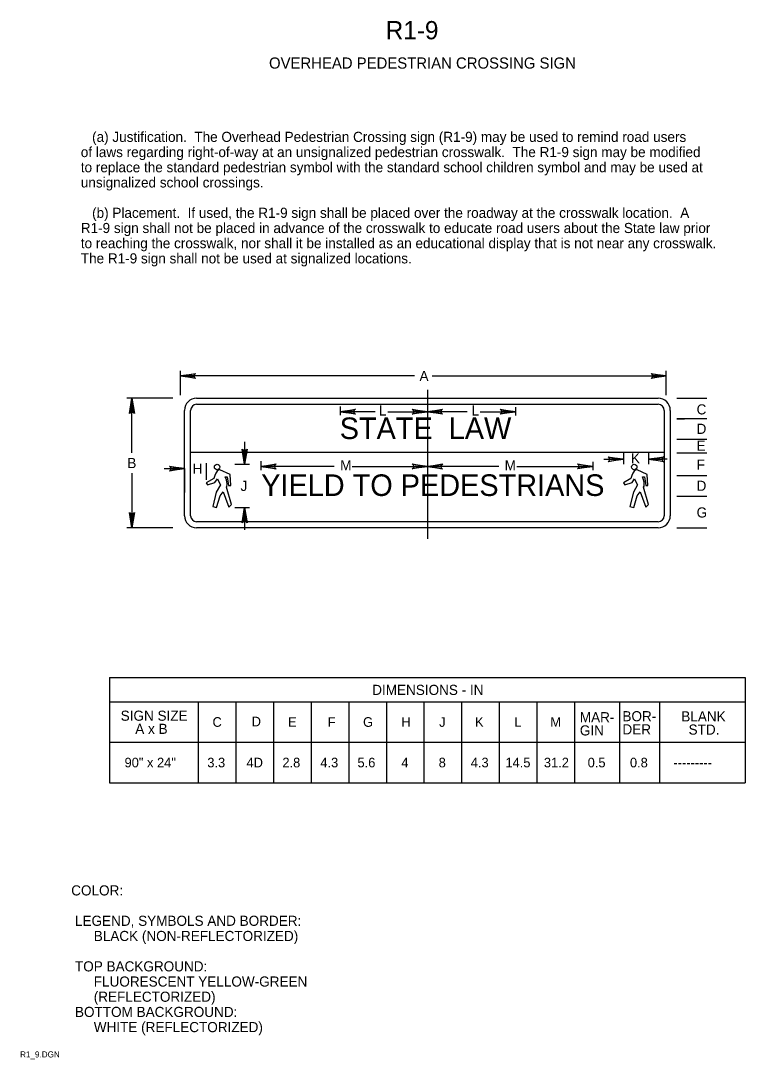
# Model space of a CAD drawing. Extents: x 0.013 to 0.192, y 0.003 to 0.259.
import ezdxf

# ---------------------------------------------------------------- set-up
doc = ezdxf.new("R2010")
doc.units = 0
for name, color, linetype in [('1', 7, 'Continuous'), ('11', 7, 'Continuous'), ('12', 7, 'Continuous'), ('2', 7, 'Continuous'), ('3', 7, 'Continuous')]:
    doc.layers.add(name, color=color, linetype=linetype)

# ---------------------------------------------------------------- blocks, each defined once
blk = doc.blocks.new('RARROW')
at = {"layer": '3'}
for p, q in [((-2.156, 0.285), (-2.2665, 0.384625)), ((-2.2665, 0.384625), (0, 0)), ((0, 0), (-2.2665, -0.379125)), ((-2.156, 0.285), (-2.075625, 0.12075)), ((0, 0), (-2.156, 0.285)), ((-2.14975, -0.2705), (0, 0)), ((-2.075625, 0.12075), (0, 0)), ((0, 0), (-2.074, -0.108)), ((-2.2665, -0.379125), (-2.14975, -0.2705)), ((-2.074, -0.108), (-2.14975, -0.2705))]:
    blk.add_line(p, q, dxfattribs=at)

msp = doc.modelspace()

# ---------------------------------------------------------------- linework, layer by layer
at = {"layer": '11'}
for p, q in [((0.05612, 0.16599), (0.17012, 0.16599)), ((0.05312, 0.13699), (0.05312, 0.16299)), ((0.17313, 0.16299), (0.17313, 0.13699)), ((0.17012, 0.13399), (0.05612, 0.13399))]:
    msp.add_line(p, q, dxfattribs=at)
for centre, start, end in [((0.05612, 0.16299), 90, 180), ((0.17012, 0.16299), 0, 90), ((0.05612, 0.13699), 180, 270), ((0.17012, 0.13699), 270, 0)]:
    msp.add_arc(centre, 0.003, start, end, dxfattribs=at)
at = {"layer": '3'}
for p, q in [((0.05212, 0.16674), (0.05212, 0.17274)), ((0.17213, 0.16674), (0.17213, 0.17274)), ((0.10992, 0.17149), (0.05212, 0.17149)), ((0.11433, 0.17149), (0.17213, 0.17149)), ((0.11313, 0.16809), (0.11313, 0.13125)), ((0.05025, 0.16599), (0.03887, 0.16599)), ((0.0395, 0.16224), (0.04013, 0.16599)), ((0.04013, 0.16599), (0.03966, 0.16242)), ((0.03993, 0.16255), (0.04013, 0.16599)), ((0.04013, 0.16599), (0.0403, 0.16255)), ((0.04057, 0.16243), (0.04013, 0.16599)), ((0.04013, 0.16599), (0.04075, 0.16224)), ((0.04013, 0.15255), (0.04013, 0.16599)), ((0.05612, 0.16449), (0.17012, 0.16449)), ((0.11313, 0.16429), (0.11313, 0.16142)), ((0.17473, 0.16599), (0.18213, 0.16599)), ((0.03966, 0.16242), (0.0395, 0.16224)), ((0.03966, 0.16242), (0.03993, 0.16255)), ((0.0403, 0.16255), (0.04057, 0.16243)), ((0.04075, 0.16224), (0.04057, 0.16243)), ((0.05462, 0.13699), (0.05462, 0.16299)), ((0.09157, 0.16394), (0.09157, 0.16177)), ((0.09657, 0.16267), (0.09157, 0.16267)), ((0.10018, 0.16267), (0.09278, 0.16267)), ((0.10339, 0.16267), (0.11122, 0.16267)), ((0.11813, 0.16267), (0.11313, 0.16267)), ((0.12296, 0.16267), (0.11313, 0.16267)), ((0.12616, 0.16267), (0.13486, 0.16267)), ((0.13486, 0.16379), (0.13486, 0.16171)), ((0.17162, 0.16299), (0.17162, 0.13699)), ((0.17473, 0.16096), (0.18213, 0.16096)), ((0.17473, 0.16094), (0.17663, 0.16094)), ((0.06796, 0.15524), (0.06796, 0.1497)), ((0.17473, 0.1559), (0.17545, 0.1559)), ((0.17473, 0.1559), (0.18213, 0.1559)), ((0.05462, 0.15266), (0.17162, 0.15266)), ((0.16154, 0.15255), (0.16154, 0.14968)), ((0.16776, 0.15257), (0.16776, 0.14969)), ((0.17473, 0.1525), (0.18213, 0.1525)), ((0.05849, 0.14998), (0.05849, 0.14584)), ((0.06558, 0.1497), (0.06921, 0.1497)), ((0.06558, 0.14969), (0.06649, 0.14969)), ((0.07199, 0.15042), (0.07199, 0.14825)), ((0.07699, 0.14914), (0.07199, 0.14914)), ((0.09012, 0.14914), (0.07321, 0.14914)), ((0.09454, 0.14914), (0.11122, 0.14914)), ((0.11313, 0.15077), (0.11313, 0.14789)), ((0.11813, 0.14914), (0.11313, 0.14914)), ((0.13075, 0.14914), (0.11313, 0.14914)), ((0.13521, 0.14914), (0.15396, 0.14914)), ((0.15396, 0.15026), (0.15396, 0.14819)), ((0.15675, 0.15093), (0.1615, 0.15093)), ((0.17233, 0.15094), (0.16776, 0.15094)), ((0.17233, 0.15094), (0.16776, 0.15094)), ((0.04013, 0.14751), (0.04013, 0.134)), ((0.04813, 0.14861), (0.05312, 0.14861)), ((0.05312, 0.14861), (0.05312, 0.14274)), ((0.06058, 0.14692), (0.06035, 0.14614)), ((0.06084, 0.14749), (0.06058, 0.14692)), ((0.06115, 0.14802), (0.06084, 0.14749)), ((0.06114, 0.14801), (0.06118, 0.14805)), ((0.06126, 0.14812), (0.06115, 0.14802)), ((0.06188, 0.14829), (0.06126, 0.14812)), ((0.06438, 0.14717), (0.06188, 0.14829)), ((0.06319, 0.1466), (0.06368, 0.14661)), ((0.06347, 0.14581), (0.06319, 0.1466)), ((0.06368, 0.14661), (0.06402, 0.14445)), ((0.06457, 0.14443), (0.06438, 0.14717)), ((0.16363, 0.14692), (0.1634, 0.14614)), ((0.16389, 0.14749), (0.16363, 0.14692)), ((0.1642, 0.14802), (0.16389, 0.14749)), ((0.16419, 0.14801), (0.16423, 0.14805)), ((0.16432, 0.14812), (0.1642, 0.14802)), ((0.16493, 0.14829), (0.16432, 0.14812)), ((0.16743, 0.14717), (0.16493, 0.14829)), ((0.16624, 0.1466), (0.16673, 0.14661)), ((0.16652, 0.14581), (0.16624, 0.1466)), ((0.16673, 0.14661), (0.16707, 0.14445)), ((0.16762, 0.14443), (0.16743, 0.14717)), ((0.17473, 0.14689), (0.18213, 0.14689)), ((0.05881, 0.14462), (0.06064, 0.14522)), ((0.06064, 0.14522), (0.06123, 0.14606)), ((0.06198, 0.14459), (0.06096, 0.14283)), ((0.06123, 0.14606), (0.06148, 0.14549)), ((0.06148, 0.14549), (0.06198, 0.14459)), ((0.06359, 0.14526), (0.06347, 0.14581)), ((0.06349, 0.14403), (0.0636, 0.14427)), ((0.06471, 0.13972), (0.06349, 0.14403)), ((0.06363, 0.14493), (0.06359, 0.14526)), ((0.0636, 0.14427), (0.06365, 0.14464)), ((0.06365, 0.14464), (0.06363, 0.14493)), ((0.06402, 0.14445), (0.06457, 0.14443)), ((0.16187, 0.14462), (0.1637, 0.14522)), ((0.1637, 0.14522), (0.16428, 0.14606)), ((0.16503, 0.14459), (0.16402, 0.14283)), ((0.16428, 0.14606), (0.16453, 0.14549)), ((0.16453, 0.14549), (0.16503, 0.14459)), ((0.16665, 0.14526), (0.16652, 0.14581)), ((0.16654, 0.14403), (0.16666, 0.14427)), ((0.16776, 0.13972), (0.16654, 0.14403)), ((0.16669, 0.14493), (0.16665, 0.14526)), ((0.16666, 0.14427), (0.1667, 0.14464)), ((0.1667, 0.14464), (0.16669, 0.14493)), ((0.16707, 0.14445), (0.16762, 0.14443)), ((0.06096, 0.14283), (0.0601, 0.1393)), ((0.06106, 0.13904), (0.06189, 0.14193)), ((0.06189, 0.14193), (0.06267, 0.14289)), ((0.06267, 0.14289), (0.06321, 0.14132)), ((0.06321, 0.14132), (0.06406, 0.13907)), ((0.16402, 0.14283), (0.16315, 0.1393)), ((0.16411, 0.13904), (0.16494, 0.14193)), ((0.16494, 0.14193), (0.16572, 0.14289)), ((0.16572, 0.14289), (0.16626, 0.14132)), ((0.16626, 0.14132), (0.16712, 0.13907)), ((0.17473, 0.14185), (0.18213, 0.14185)), ((0.06558, 0.13901), (0.06921, 0.13901)), ((0.06796, 0.13901), (0.06796, 0.13347)), ((0.05025, 0.134), (0.03887, 0.134)), ((0.17012, 0.13549), (0.05612, 0.13549)), ((0.17473, 0.13399), (0.18213, 0.13399)), ((0.0346, 0.09704), (0.0346, 0.07104)), ((0.0346, 0.09704), (0.19165, 0.09704)), ((0.19165, 0.09704), (0.19165, 0.07104)), ((0.0346, 0.09104), (0.19165, 0.09104)), ((0.05648, 0.09104), (0.05648, 0.07104)), ((0.06578, 0.09104), (0.06578, 0.07104)), ((0.07508, 0.09104), (0.07508, 0.07104)), ((0.08438, 0.09104), (0.08438, 0.07104)), ((0.09368, 0.09104), (0.09368, 0.07104)), ((0.10298, 0.09104), (0.10298, 0.07104)), ((0.11228, 0.09104), (0.11228, 0.07104)), ((0.12158, 0.09104), (0.12158, 0.07104)), ((0.13088, 0.09104), (0.13088, 0.07104)), ((0.14018, 0.09104), (0.14018, 0.07104)), ((0.14948, 0.09104), (0.14948, 0.07104)), ((0.16056, 0.09104), (0.16056, 0.07104)), ((0.1705, 0.09104), (0.1705, 0.07104)), ((0.0346, 0.08104), (0.19165, 0.08104)), ((0.0346, 0.07104), (0.19165, 0.07104))]:
    msp.add_line(p, q, dxfattribs=at)
for points in [[(0.05881, 0.14462), (0.06064, 0.14522), (0.06123, 0.14606), (0.06148, 0.14549), (0.06198, 0.14459), (0.06096, 0.14283), (0.0601, 0.1393), (0.06106, 0.13904), (0.06189, 0.14193), (0.06267, 0.14289), (0.06321, 0.14132), (0.06406, 0.13907), (0.06471, 0.13972), (0.06349, 0.14403), (0.0636, 0.14427), (0.06365, 0.14464), (0.06363, 0.14493), (0.06359, 0.14526), (0.06347, 0.14581), (0.06319, 0.1466), (0.06368, 0.14661), (0.06402, 0.14445), (0.06457, 0.14443), (0.06438, 0.14717), (0.06188, 0.14829), (0.06126, 0.14812), (0.06084, 0.14749), (0.06058, 0.14692), (0.06035, 0.14614), (0.05849, 0.14508), (0.05881, 0.14462)], [(0.16187, 0.14462), (0.1637, 0.14522), (0.16428, 0.14606), (0.16453, 0.14549), (0.16503, 0.14459), (0.16402, 0.14283), (0.16315, 0.1393), (0.16411, 0.13904), (0.16494, 0.14193), (0.16572, 0.14289), (0.16626, 0.14132), (0.16712, 0.13907), (0.16776, 0.13972), (0.16654, 0.14403), (0.16666, 0.14427), (0.1667, 0.14464), (0.16669, 0.14493), (0.16665, 0.14526), (0.16652, 0.14581), (0.16624, 0.1466), (0.16673, 0.14661), (0.16707, 0.14445), (0.16762, 0.14443), (0.16743, 0.14717), (0.16493, 0.14829), (0.16432, 0.14812), (0.16389, 0.14749), (0.16363, 0.14692), (0.1634, 0.14614), (0.16155, 0.14508), (0.16187, 0.14462)]]:
    msp.add_lwpolyline(points, dxfattribs=at)
for centre in [(0.06117, 0.14902), (0.16423, 0.14902)]:
    msp.add_circle(centre, 0.000672, dxfattribs=at)
for centre, start, end in [((0.05612, 0.16299), 90, 180), ((0.17012, 0.16299), 0, 90), ((0.05612, 0.13699), 180, 270), ((0.17012, 0.13699), 270, 0)]:
    msp.add_arc(centre, 0.0015, start, end, dxfattribs=at)

# ---------------------------------------------------------------- block references
at = {"layer": '3', "xscale": 0.0016545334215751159, "yscale": 0.0016366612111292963}
for p, rotation in [((0.05212, 0.17149), 180), ((0.09157, 0.16267), 180), ((0.11313, 0.16267), 180), ((0.06796, 0.1497), -90), ((0.16776, 0.15094), 180), ((0.07199, 0.14914), 180), ((0.11313, 0.14914), 180), ((0.06796, 0.13901), 90), ((0.04013, 0.134), -90)]:
    msp.add_blockref('RARROW', p, dxfattribs=dict(at, rotation=rotation))
for p in [(0.17213, 0.17149), (0.11313, 0.16267), (0.13486, 0.16267), (0.1615, 0.15093), (0.05312, 0.14861), (0.11313, 0.14914), (0.15396, 0.14914)]:
    msp.add_blockref('RARROW', p, dxfattribs=at)

# ---------------------------------------------------------------- texts
at = {"layer": '1'}
for s, height, p in [('R1-9', 0.0045, (0.10282, 0.25462)), ('OVERHEAD PEDESTRIAN CROSSING SIGN', 0.0027503, (0.074, 0.24738)), ('COLOR:', 0.0025, (0.02513, 0.04322)), (' LEGEND, SYMBOLS AND BORDER:', 0.0024998, (0.02513, 0.03572)), ('      BLACK (NON-REFLECTORIZED)', 0.0024998, (0.02513, 0.03197)), (' TOP BACKGROUND:', 0.0024998, (0.02513, 0.02447)), ('      FLUORESCENT YELLOW-GREEN', 0.0024998, (0.02513, 0.02072)), ('      (REFLECTORIZED)', 0.0024998, (0.02513, 0.01697)), (' BOTTOM BACKGROUND:', 0.0024998, (0.02513, 0.01322)), ('      WHITE (REFLECTORIZED)', 0.0024998, (0.02513, 0.00947)), ('R1_9.DGN', 0.0015, (0.0125, 0.00322))]:
    msp.add_text(s, height=height, dxfattribs=at).set_placement(p)
at = {"layer": '12'}
for s, p in [('STATE  LAW', (0.09146, 0.15591)), ('YIELD TO PEDESTRIANS', (0.07207, 0.14186))]:
    msp.add_text(s, height=0.005332, dxfattribs=at).set_placement(p)
at = {"layer": '2'}
for s, height, p in [('   (a) Justification.  The Overhead Pedestrian Crossing sign (R1-9) may be used to remind road users', 0.0024998, (0.0275, 0.22928)), ('of laws regarding right-of-way at an unsignalized pedestrian crosswalk.  The R1-9 sign may be modified ', 0.00249975, (0.0275, 0.22553)), ('to replace the standard pedestrian symbol with the standard school children symbol and may be used at', 0.00249975, (0.0275, 0.22178)), ('unsignalized school crossings. ', 0.0024998, (0.0275, 0.21803)), ('   (b) Placement.  If used, the R1-9 sign shall be placed over the roadway at the crosswalk location.  A ', 0.00249975, (0.0275, 0.21053)), ('R1-9 sign shall not be placed in advance of the crosswalk to educate road users about the State law prior ', 0.00249975, (0.0275, 0.20678)), ('to reaching the crosswalk, nor shall it be installed as an educational display that is not near any crosswalk.  ', 0.00249975, (0.0275, 0.20303)), ('The R1-9 sign shall not be used at signalized locations.', 0.0024998, (0.0275, 0.19928))]:
    msp.add_text(s, height=height, dxfattribs=at).set_placement(p)
at = {"layer": '3'}
for s, height, p in [('A', 0.0025, (0.11117, 0.17024)), ('L', 0.0025, (0.10114, 0.16172)), ('L', 0.0025, (0.12401, 0.1617)), ('C', 0.0025, (0.17963, 0.16199)), ('D', 0.0025, (0.17963, 0.15719)), ('E', 0.0025, (0.17963, 0.15302)), ('K', 0.0025, (0.16342, 0.14992)), ('B', 0.0025, (0.039, 0.14874)), ('H', 0.0025, (0.05512, 0.14735)), ('M', 0.0025, (0.09159, 0.14819)), ('M', 0.0025, (0.13221, 0.14817)), ('F', 0.0025, (0.17963, 0.14836)), ('J', 0.0025, (0.06696, 0.1431)), ('D', 0.0025, (0.17963, 0.14313)), ('G', 0.0025, (0.17963, 0.13654)), ('DIMENSIONS - IN', 0.0024998, (0.09949, 0.09273)), ('SIGN SIZE', 0.0025, (0.03735, 0.08636)), ('C', 0.00238, (0.06004, 0.08486)), ('D', 0.00238, (0.06972, 0.08498)), ('E', 0.00238, (0.0787, 0.08486)), ('F', 0.00238, (0.0885, 0.08486)), ('G', 0.00238, (0.09723, 0.08486)), ('H', 0.00238, (0.10668, 0.08486)), ('J', 0.00238, (0.11603, 0.08486)), ('K', 0.00238, (0.1249, 0.08486)), ('L', 0.00238, (0.1346, 0.08486)), ('M', 0.00238, (0.14349, 0.08486)), ('MAR-', 0.0025, (0.15078, 0.08598)), ('BOR-', 0.0025, (0.16131, 0.08623)), ('BLANK', 0.0025, (0.17585, 0.08618)), ('A x B', 0.0025, (0.04095, 0.08311)), ('GIN', 0.0025, (0.15078, 0.08273)), ('DER', 0.0025, (0.16131, 0.08298)), ('STD.', 0.0025, (0.17765, 0.08293)), ('90" x 24"', 0.002375, (0.03831, 0.07485)), ('3.3', 0.002375, (0.05875, 0.07485)), ('4D', 0.002375, (0.06844, 0.07485)), ('2.8', 0.002375, (0.0773, 0.07485)), ('4.3', 0.002375, (0.08668, 0.07485)), ('5.6', 0.002375, (0.09585, 0.07485)), ('4', 0.00238, (0.10669, 0.07485)), ('8', 0.00238, (0.11591, 0.07485)), ('4.3', 0.002375, (0.12384, 0.07485)), ('14.5', 0.002375, (0.13241, 0.07485)), ('31.2', 0.002375, (0.1419, 0.07485)), ('0.5', 0.002375, (0.15272, 0.07485)), ('0.8', 0.002375, (0.16316, 0.07485)), ('---------', 0.002375, (0.17391, 0.07485))]:
    msp.add_text(s, height=height, dxfattribs=at).set_placement(p)

doc.saveas('drawing.dxf')
